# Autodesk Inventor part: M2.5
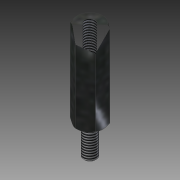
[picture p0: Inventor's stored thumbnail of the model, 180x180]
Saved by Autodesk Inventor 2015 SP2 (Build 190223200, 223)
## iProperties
Created: 2012-08
Part Number: M2.5
Material: Stahl
Document SubType Name: Modeling
Designer: rYan
Density: 7.85 g/cm^3
Mass: 1.74537 g
Surface Area: 3.04272 cm^2
Volume: 0.22234 cm^3
Appearance: Platte
Author: rYan
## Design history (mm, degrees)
derived "Abstandsbolzen Typ B.ipt"
feature "Volumenkörper1::Abstandsbolzen Typ B.ipt"
tag "Bezeichnung1"
node "Volumenkörper1"
other parameters: "SW" = 5, "L" = 17, "d2" = 0, "l_" = 7, "d9" = 118 deg, "GA_" = 2.5, "A_" = 6, "d13" = 0, "d17" = 0.25, "d20" = 45 deg
